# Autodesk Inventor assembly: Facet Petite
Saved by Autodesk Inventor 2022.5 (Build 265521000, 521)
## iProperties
Created: 2024-07
Part Number: Facet Petite
Document SubType Name: Assembly
Designer: AdminForWorker
Title: Facet Petite v6
Author: AdminForWorker
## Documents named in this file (2)
- z:\worker\convert-fusion-r03-cosv3\tmp\job-1\6\temp\files\4192786e-9465-4c09-abb0-424b8e2f5858\Facet Petite v6.iam
- z:\worker\convert-fusion-r03-cosv3\tmp\job-1\6\temp\files\4192786e-9465-4c09-abb0-424b8e2f5858\Facet Petite.ipt
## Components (1 placed, 1 different names)
1. Facet Petite:1
